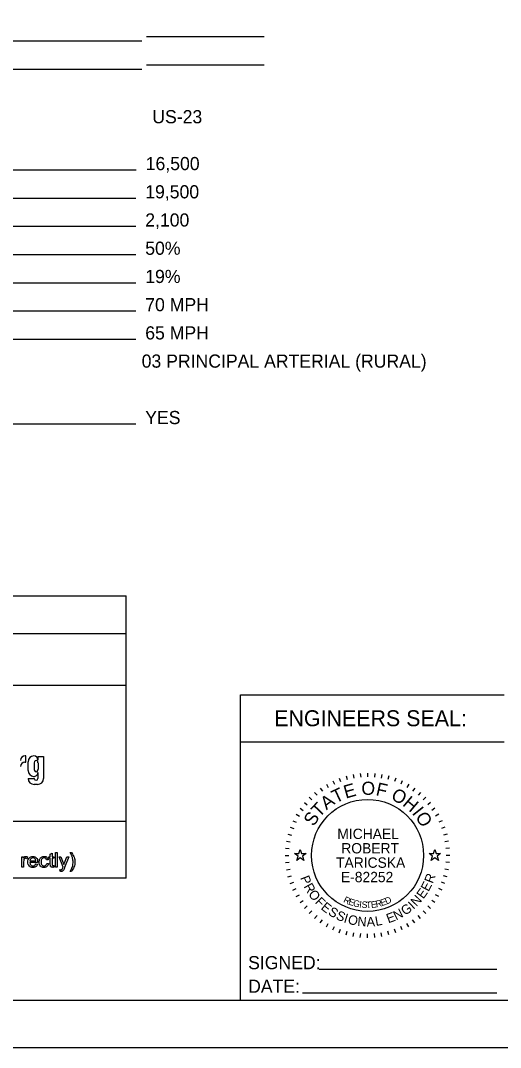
# Model space of a CAD drawing. Extents: x -17 to 88, y -5 to 22.
# Drawn here: x 6.91 to 12.01, y 0 to 10.92 of the extents above; entities that cross this region are included whole.
import ezdxf

# ---------------------------------------------------------------- set-up
doc = ezdxf.new("R2010")
doc.units = 0
for name, color, linetype in [('SH_Border', 7, 'Continuous'), ('SH_Cut_Line', 7, 'Continuous'), ('SH_Data', 7, 'Continuous'), ('TX_P_10', 7, 'Continuous')]:
    doc.layers.add(name, color=color, linetype=linetype)

msp = doc.modelspace()

# ---------------------------------------------------------------- linework, layer by layer
at = {"layer": 'SH_Border'}
msp.add_lwpolyline([(2, 21.5), (33.5, 21.5), (33.5, 0.5), (2, 0.5)], close=True, dxfattribs=at)
at = {"layer": 'SH_Cut_Line'}
msp.add_lwpolyline([(0, 0), (34, 0), (34, 22), (0, 22)], close=True, dxfattribs=at)
at = {"layer": 'SH_Data'}
for p, q in [((9.5, 10.743), (8.25, 10.743)), ((8.2, 10.697), (5.424, 10.697)), ((8.2, 10.397), (3.935, 10.397)), ((9.5, 10.443), (8.25, 10.443)), ((8.142, 9.327), (4.574, 9.327)), ((8.137, 9.027), (4.999, 9.027)), ((8.137, 8.727), (5.676, 8.727)), ((8.137, 8.427), (5.371, 8.427)), ((8.137, 8.127), (4.875, 8.127)), ((8.137, 7.827), (3.942, 7.827)), ((8.137, 7.527), (3.851, 7.527)), ((8.137, 6.627), (3.912, 6.627)), ((3.285, 4.801), (8.035, 4.801)), ((8.035, 1.801), (8.035, 4.801)), ((3.285, 4.401), (8.035, 4.401)), ((3.285, 3.851), (8.035, 3.851)), ((9.25, 0.5), (9.25, 3.75)), ((9.25, 3.75), (12.05, 3.75)), ((9.25, 3.25), (12.05, 3.25)), ((6.968, 3.101), (6.962, 3.101)), ((6.968, 3.033), (6.968, 3.101)), ((7.098, 3.053), (7.098, 3.095)), ((7.098, 3.095), (7.157, 3.095)), ((7.157, 3.095), (7.157, 2.86)), ((6.957, 3.033), (6.968, 3.033)), ((6.993, 2.944), (6.993, 3.038)), ((7.059, 2.956), (7.059, 3.026)), ((7.098, 3.026), (7.098, 2.956)), ((6.993, 2.86), (7.059, 2.86)), ((7.098, 2.86), (7.098, 2.923)), ((10.299, 2.864), (10.313, 2.826)), ((10.372, 2.887), (10.383, 2.848)), ((10.447, 2.903), (10.454, 2.864)), ((10.522, 2.913), (10.526, 2.873)), ((10.599, 2.917), (10.599, 2.877)), ((10.675, 2.913), (10.671, 2.873)), ((10.751, 2.903), (10.744, 2.864)), ((10.825, 2.887), (10.815, 2.848)), ((10.898, 2.864), (10.884, 2.826)), ((7.093, 2.797), (7.057, 2.797)), ((10.097, 2.758), (10.12, 2.726)), ((10.161, 2.799), (10.181, 2.765)), ((10.229, 2.835), (10.246, 2.798)), ((10.968, 2.835), (10.952, 2.798)), ((11.036, 2.799), (11.016, 2.765)), ((11.101, 2.758), (11.078, 2.726)), ((9.98, 2.66), (10.008, 2.632)), ((10.036, 2.712), (10.062, 2.681)), ((11.161, 2.712), (11.135, 2.681)), ((11.217, 2.66), (11.189, 2.632)), ((9.882, 2.543), (9.915, 2.52)), ((9.928, 2.604), (9.959, 2.578)), ((11.269, 2.604), (11.238, 2.578)), ((11.315, 2.543), (11.283, 2.52)), ((9.806, 2.411), (9.842, 2.394)), ((9.841, 2.479), (9.876, 2.459)), ((11.356, 2.479), (11.322, 2.459)), ((11.392, 2.411), (11.355, 2.394)), ((8.035, 2.401), (3.285, 2.401)), ((9.776, 2.341), (9.814, 2.327)), ((11.421, 2.341), (11.383, 2.327)), ((9.737, 2.193), (9.776, 2.187)), ((9.753, 2.268), (9.792, 2.258)), ((11.444, 2.268), (11.405, 2.258)), ((11.46, 2.193), (11.421, 2.187)), ((9.727, 2.118), (9.767, 2.114)), ((11.47, 2.118), (11.431, 2.114)), ((9.724, 2.042), (9.764, 2.042)), ((9.727, 1.965), (9.767, 1.969)), ((11.47, 1.965), (11.431, 1.969)), ((11.474, 2.042), (11.434, 2.042)), ((9.737, 1.89), (9.776, 1.897)), ((11.46, 1.89), (11.421, 1.897)), ((8.035, 1.801), (3.285, 1.801)), ((9.753, 1.815), (9.792, 1.825)), ((9.776, 1.742), (9.814, 1.756)), ((11.421, 1.742), (11.383, 1.756)), ((11.444, 1.815), (11.405, 1.825)), ((9.806, 1.672), (9.842, 1.689)), ((11.392, 1.672), (11.355, 1.689)), ((9.841, 1.604), (9.876, 1.624)), ((9.882, 1.54), (9.915, 1.563)), ((11.315, 1.54), (11.283, 1.563)), ((11.356, 1.604), (11.322, 1.624)), ((9.928, 1.479), (9.959, 1.505)), ((9.98, 1.423), (10.008, 1.451)), ((11.217, 1.423), (11.189, 1.451)), ((11.269, 1.479), (11.238, 1.505)), ((10.036, 1.371), (10.062, 1.402)), ((10.097, 1.325), (10.12, 1.358)), ((10.161, 1.284), (10.181, 1.318)), ((11.036, 1.284), (11.016, 1.318)), ((11.101, 1.325), (11.078, 1.358)), ((11.161, 1.371), (11.135, 1.402)), ((10.229, 1.249), (10.246, 1.285)), ((10.299, 1.219), (10.313, 1.257)), ((10.372, 1.196), (10.383, 1.235)), ((10.447, 1.18), (10.454, 1.219)), ((10.522, 1.17), (10.526, 1.21)), ((10.599, 1.167), (10.599, 1.207)), ((10.675, 1.17), (10.671, 1.21)), ((10.751, 1.18), (10.744, 1.219)), ((10.825, 1.196), (10.815, 1.235)), ((10.898, 1.219), (10.884, 1.257)), ((10.968, 1.249), (10.952, 1.285)), ((10.086, 0.832), (11.971, 0.832)), ((9.908, 0.581), (11.971, 0.581))]:
    msp.add_line(p, q, dxfattribs=at)
for points in [[(9.822, 2.062), (9.869, 2.062), (9.884, 2.106), (9.898, 2.062), (9.945, 2.062), (9.907, 2.034), (9.922, 1.989), (9.884, 2.017), (9.846, 1.989), (9.86, 2.034)], [(11.252, 2.062), (11.299, 2.062), (11.314, 2.106), (11.328, 2.062), (11.375, 2.062), (11.337, 2.034), (11.352, 1.989), (11.314, 2.017), (11.276, 1.989), (11.29, 2.034)]]:
    msp.add_lwpolyline(points, close=True, dxfattribs=at)
for points in [[(6.926, 1.917), (6.926, 2.028), (6.943, 2.028), (6.943, 2.011)], [(6.945, 1.975), (6.945, 1.917), (6.926, 1.917)], [(6.986, 2.025), (6.98, 2.007)], [(7.094, 1.968), (7.011, 1.968)], [(7.012, 1.983), (7.074, 1.983)], [(7.207, 1.995), (7.188, 1.993)], [(7.228, 1.949), (7.228, 2.014), (7.214, 2.014), (7.214, 2.028), (7.228, 2.028), (7.228, 2.056), (7.247, 2.067), (7.247, 2.028), (7.266, 2.028), (7.266, 2.014), (7.247, 2.014), (7.247, 1.948)], [(7.284, 1.917), (7.284, 2.071), (7.303, 2.071), (7.303, 1.917), (7.284, 1.917)], [(7.364, 1.916), (7.322, 2.028), (7.342, 2.028), (7.365, 1.964)], [(7.381, 1.963), (7.405, 2.028), (7.424, 2.028), (7.381, 1.915)], [(7.439, 2.073), (7.452, 2.073)], [(7.074, 1.953), (7.093, 1.95)], [(7.19, 1.957), (7.209, 1.955)], [(7.266, 1.933), (7.269, 1.917)], [(7.332, 1.874), (7.329, 1.891)], [(7.452, 1.871), (7.439, 1.871)]]:
    msp.add_lwpolyline(points, dxfattribs=at)
msp.add_circle((10.599, 2.042), 0.595, dxfattribs=at)
for centre, radius, start, end in [((6.962, 3.051), 0.0498, 90, 180), ((7.056, 3.038), 0.0623, 92.6865, 180), ((7.05, 3.053), 0.0476, 0, 86.9262), ((6.957, 2.988), 0.0448, 90, 180), ((7.056, 2.944), 0.0629, 180, 265.7132), ((7.057, 2.86), 0.0635, 180, 270), ((7.055, 2.923), 0.0424, 264.7825, 0), ((7.093, 2.86), 0.0635, 270, 0)]:
    msp.add_arc(centre, radius, start, end, dxfattribs=at)
for centre, major_axis, ratio, start_param, end_param in [((7.078, 3.026), (0, 0.025), 0.777179, 4.712389, 7.853982), ((7.078, 2.956), (0, 0.025), 0.777179, 1.570796, 4.712389), ((7.078, 2.86), (0.0194, 0), 0.959012, 3.141593, 6.283185)]:
    msp.add_ellipse(centre, major_axis=major_axis, ratio=ratio, start_param=start_param, end_param=end_param, dxfattribs=at)
for points in [[(6.943, 2.011), (6.949, 2.023), (6.955, 2.027), (6.96, 2.031), (6.967, 2.031), (6.976, 2.031), (6.986, 2.025)], [(6.98, 2.007), (6.973, 2.011), (6.966, 2.011), (6.96, 2.011), (6.955, 2.007), (6.95, 2.004), (6.948, 1.997), (6.945, 1.987), (6.945, 1.975)], [(7.093, 1.95), (7.089, 1.933), (7.076, 1.924), (7.064, 1.914), (7.044, 1.914), (7.02, 1.914), (7.006, 1.929), (6.991, 1.944), (6.991, 1.971), (6.991, 2), (7.006, 2.015), (7.02, 2.031), (7.043, 2.031), (7.066, 2.031), (7.08, 2.015), (7.094, 2), (7.094, 1.973), (7.094, 1.971), (7.094, 1.968)], [(7.011, 1.968), (7.012, 1.949), (7.021, 1.939), (7.031, 1.93), (7.045, 1.93), (7.055, 1.93), (7.062, 1.935), (7.07, 1.941), (7.074, 1.953)], [(7.074, 1.983), (7.073, 1.997), (7.067, 2.004), (7.058, 2.015), (7.044, 2.015), (7.031, 2.015), (7.022, 2.006), (7.013, 1.998), (7.012, 1.983)], [(7.209, 1.955), (7.206, 1.936), (7.193, 1.925), (7.181, 1.914), (7.162, 1.914), (7.139, 1.914), (7.125, 1.929), (7.111, 1.944), (7.111, 1.972), (7.111, 1.99), (7.117, 2.004), (7.123, 2.017), (7.136, 2.024), (7.148, 2.031), (7.162, 2.031), (7.181, 2.031), (7.192, 2.021), (7.204, 2.012), (7.207, 1.995)], [(7.188, 1.993), (7.186, 2.004), (7.179, 2.009), (7.173, 2.015), (7.163, 2.015), (7.149, 2.015), (7.14, 2.005), (7.131, 1.995), (7.131, 1.972), (7.131, 1.95), (7.14, 1.94), (7.148, 1.93), (7.162, 1.93), (7.173, 1.93), (7.181, 1.936), (7.188, 1.943), (7.19, 1.957)], [(7.439, 1.871), (7.47, 1.922), (7.47, 1.972), (7.47, 1.992), (7.466, 2.011), (7.462, 2.027), (7.456, 2.042), (7.452, 2.051), (7.439, 2.073)], [(7.452, 2.073), (7.472, 2.047), (7.482, 2.02), (7.49, 1.997), (7.49, 1.972), (7.49, 1.944), (7.479, 1.917), (7.468, 1.891), (7.452, 1.871)], [(7.269, 1.917), (7.261, 1.915), (7.254, 1.915), (7.244, 1.915), (7.239, 1.918), (7.233, 1.922), (7.231, 1.927), (7.228, 1.932), (7.228, 1.949)], [(7.247, 1.948), (7.247, 1.94), (7.248, 1.938), (7.249, 1.935), (7.251, 1.934), (7.254, 1.933), (7.258, 1.933), (7.261, 1.933), (7.266, 1.933)], [(7.329, 1.891), (7.336, 1.89), (7.34, 1.89), (7.347, 1.89), (7.35, 1.892), (7.354, 1.894), (7.357, 1.898), (7.358, 1.901), (7.362, 1.912), (7.363, 1.913), (7.364, 1.916)], [(7.381, 1.915), (7.375, 1.896), (7.371, 1.889), (7.366, 1.88), (7.359, 1.876), (7.353, 1.871), (7.344, 1.871), (7.338, 1.871), (7.332, 1.874)], [(7.365, 1.964), (7.37, 1.952), (7.373, 1.938), (7.377, 1.951), (7.381, 1.963)]]:
    msp.add_open_spline(points, degree=3, dxfattribs=at)

# ---------------------------------------------------------------- texts
for s, height, p in [('16,500', 0.14, (8.242, 9.327)), ('19,500', 0.14, (8.237, 9.027)), ('2,100', 0.14, (8.237, 8.727)), ('50%', 0.14, (8.237, 8.427)), ('19%', 0.14, (8.237, 8.127)), ('70 MPH', 0.14, (8.237, 7.827)), ('65 MPH', 0.14, (8.237, 7.527)), ('YES', 0.14, (8.237, 6.627)), ('ENGINEERS SEAL:', 0.17, (9.607, 3.415)), ('MICHAEL', 0.11, (10.278, 2.216)), ('ROBERT', 0.11, (10.32, 2.063)), ('TARICSKA', 0.11, (10.264, 1.91)), ('E-82252', 0.11, (10.316, 1.757)), ('SIGNED:', 0.14, (9.33, 0.832)), ('DATE:', 0.14, (9.33, 0.581))]:
    msp.add_text(s, height=height, dxfattribs=at).set_placement(p)
for s, height, rotation, p in [('T', 0.14, 25.7167, (10.26, 2.593)), ('E', 0.14, 15.7571, (10.367, 2.645)), ('O', 0.14, 359.7812, (10.533, 2.686)), ('F', 0.14, 347.4362, (10.68, 2.683)), ('O', 0.14, 332.2586, (10.839, 2.643)), ('A', 0.14, 36.4747, (10.162, 2.52)), ('H', 0.14, 319.9136, (10.962, 2.578)), ('T', 0.14, 46.4344, (10.087, 2.438)), ('I', 0.14, 308.367, (11.065, 2.49)), ('S', 0.14, 57.1924, (10.027, 2.343)), ('O', 0.14, 303.1491, (11.101, 2.45)), ('P', 0.1, 291.494, (9.881, 1.804)), ('R', 0.1, 298.7311, (9.918, 1.713)), ('E', 0.1, 61.9951, (11.246, 1.651)), ('R', 0.1, 69.2322, (11.291, 1.737)), ('O', 0.1, 306.4666, (9.964, 1.63)), ('E', 0.1, 54.758, (11.192, 1.573)), ('F', 0.1, 314.7068, (10.033, 1.54)), ('E', 0.1, 321.4393, (10.096, 1.476)), ('R', 0.07, 334.487, (10.336, 1.547)), ('E', 0.07, 341.04, (10.389, 1.522)), ('G', 0.07, 347.4752, (10.44, 1.503)), ('I', 0.07, 353.7858, (10.508, 1.488)), ('S', 0.07, 356.8926, (10.534, 1.484)), ('T', 0.07, 3.0061, (10.584, 1.48)), ('E', 0.07, 6.0117, (10.638, 1.483)), ('R', 0.07, 11.9184, (10.691, 1.489)), ('E', 0.07, 17.6836, (10.748, 1.502)), ('D', 0.07, 23.3052, (10.8, 1.519)), ('I', 0.1, 43.287, (11.086, 1.463)), ('N', 0.1, 47.0224, (11.119, 1.492)), ('S', 0.1, 328.6764, (10.173, 1.417)), ('S', 0.1, 335.9134, (10.255, 1.368)), ('I', 0.1, 343.1505, (10.339, 1.331)), ('E', 0.1, 20.0742, (10.82, 1.319)), ('N', 0.1, 27.3113, (10.903, 1.349)), ('G', 0.1, 35.0469, (10.997, 1.399)), ('O', 0.1, 346.8859, (10.383, 1.317)), ('N', 0.1, 355.1261, (10.488, 1.293)), ('A', 0.1, 2.8617, (10.591, 1.285)), ('L', 0.1, 10.0987, (10.688, 1.291))]:
    msp.add_text(s, height=height, rotation=rotation, dxfattribs=at).set_placement(p)
at = {"layer": 'TX_P_10'}
for s, p in [('US-23', (8.312, 9.825)), ('03 PRINCIPAL ARTERIAL (RURAL) ', (8.199, 7.227))]:
    msp.add_text(s, height=0.14, dxfattribs=at).set_placement(p)

doc.saveas('drawing.dxf')
